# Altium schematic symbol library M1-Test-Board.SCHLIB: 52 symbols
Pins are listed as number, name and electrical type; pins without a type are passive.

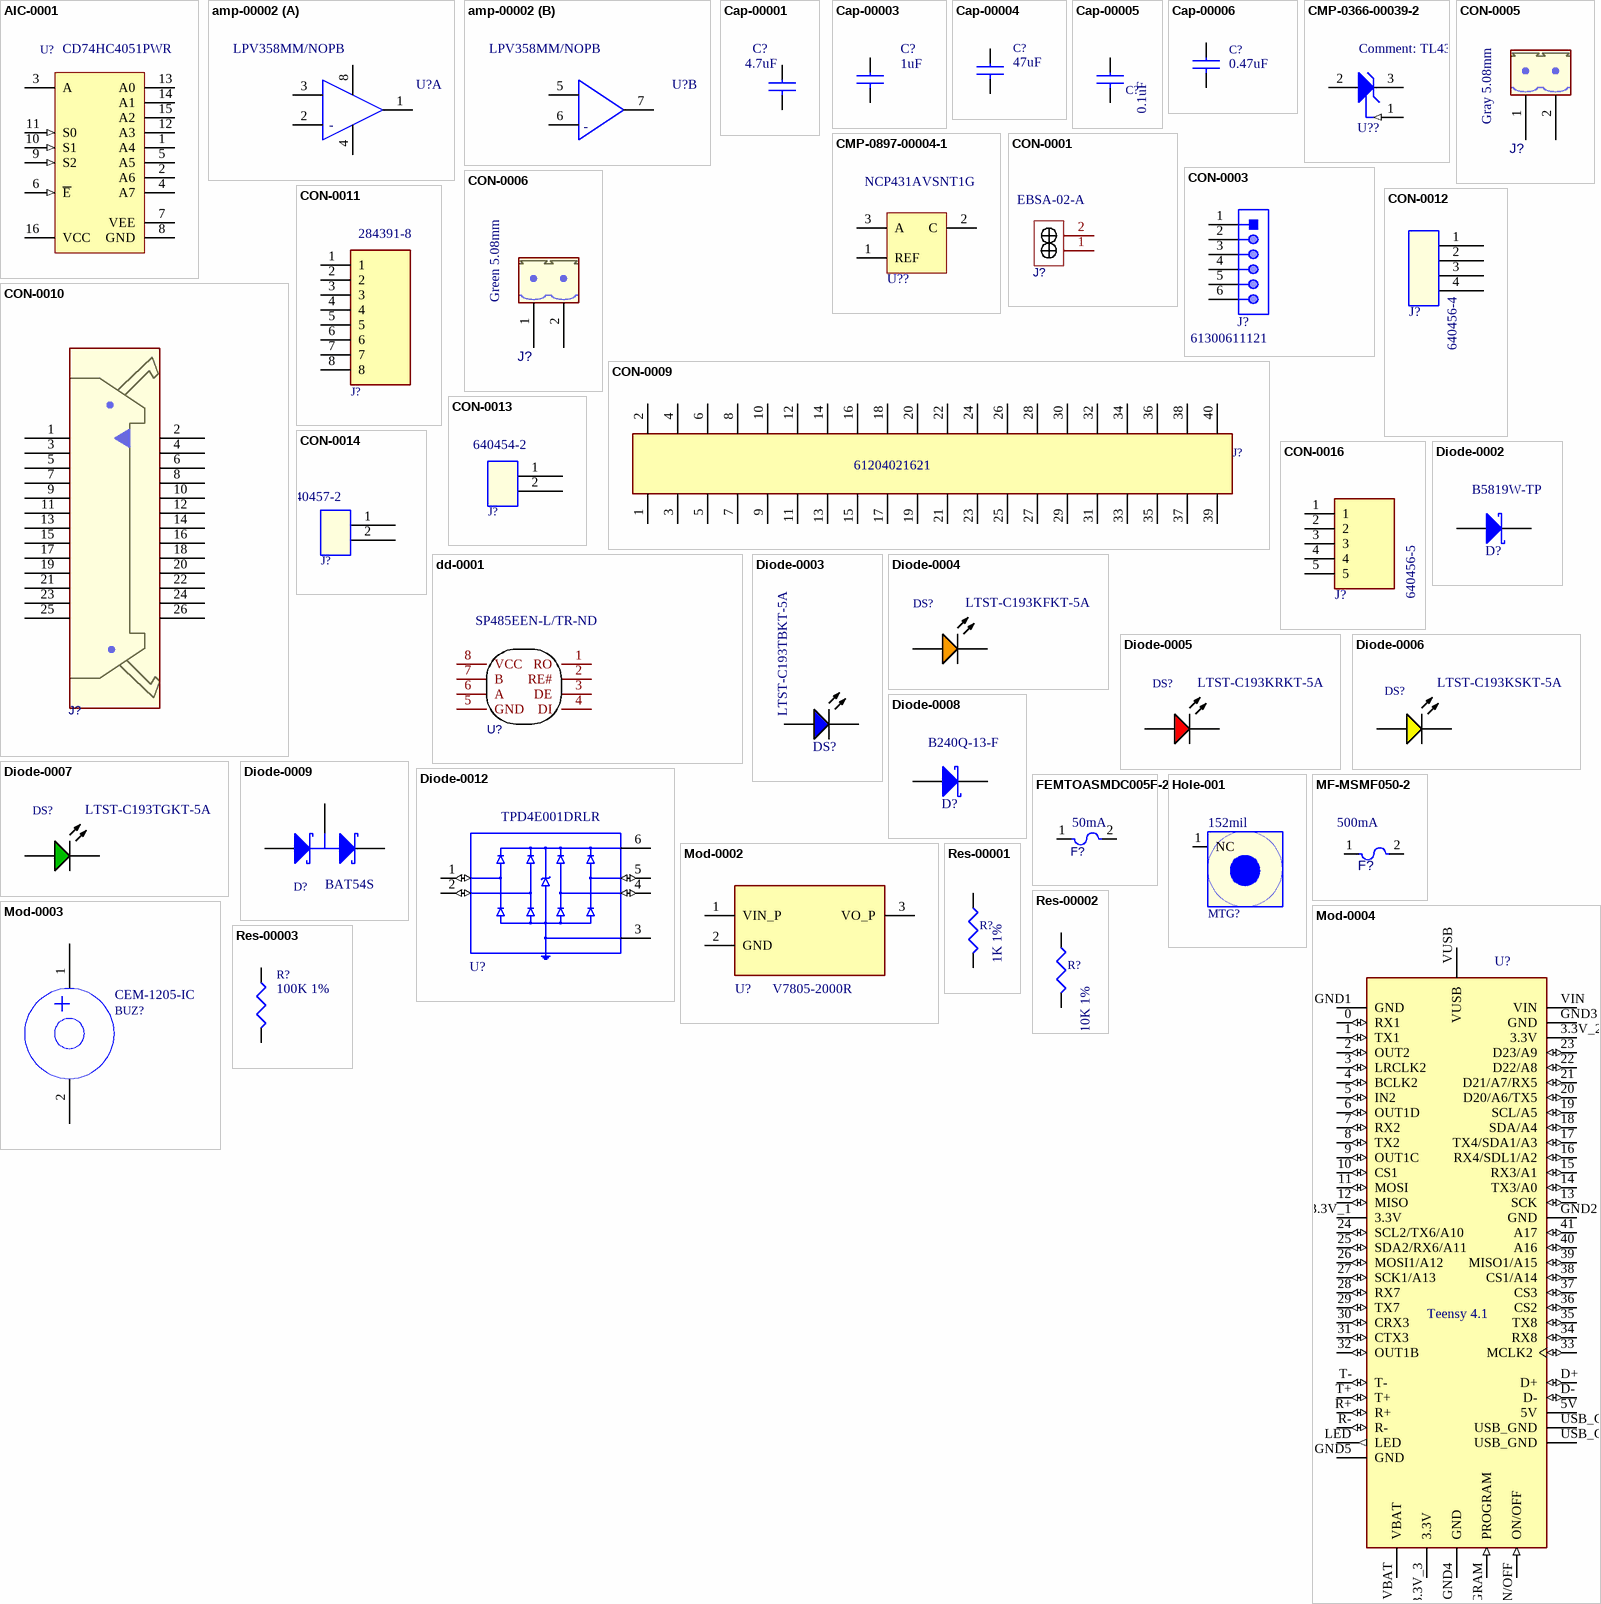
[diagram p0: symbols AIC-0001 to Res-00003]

## AIC-0001
designator U?, comment CD74HC4051PWR
5-V, 8: 1, 1-channel analog mutliplexer 16-TS; Manufacturer: Texas Instruments; Output Type: CMOS; VCC(Max)(V): 6; Ron(Typ)(Ohms): 45; Rating: Catalog; VCC(Min)(V): 2; Ron(Max)(Ohms): 130; Configuration: 1 X 1：8 MUX; Crosstalk: Yes; Bandwidth(Max)(MHz): 180; Bandwidth: 180MHz; Propagation Delay: 60ns; Number of Outputs: 1; Max Supply Voltage: 6V; Min Supply Voltage: 2V; Number of Inputs: 8; Min Dual Supply Voltage: 1V; Max Dual Supply Voltage: 5V; Dual Supply Voltage: 3V; Logic Function: Multiplexer,Demultiplexer; On-State Resistance: 130R; Turn-On Delay Time: 225ns; Supply Type: Single,Dual; Nominal Supply Current: 16uA; Polarity: Non-Inverting; Low Level Output Current: 25mA
footprint D0016A_N (SOIC, 16-Leads, Body 10x4mm, Pitch 1.27mm, IPC Medium Density)
footprint D0016A_L (SOIC, 16-Leads, Body 10x4mm, Pitch 1.27mm, IPC High Density)
footprint D0016A_M (SOIC, 16-Leads, Body 10x4mm, Pitch 1.27mm, IPC Low Density)
footprint 16-TSSOP-4.4mm
pins: 1 A4, 2 A6, 3 A, 4 A7, 5 A5, 6 ~{E} (in), 7 VEE (power), 8 GND (power), 9 S2 (in), 10 S1 (in), 11 S0 (in), 12 A3, 13 A0, 14 A1, 15 A2, 16 VCC (power)

## amp-00002
designator U?, comment LPV358MM/NOPB
Op Amp Dual Micropower Amplifier R-R O/P 5V 8; Manufacturer: TI National Semiconductor; Manufacturer: Texas Instruments; Manufacturer Part Number: LM358DR; Part Name: amp-00002; Output Current: 2mA; Min Dual Supply Voltage: 1.5V; Input Offset Voltage (Vos): 1.5mV; Power Supply Rejection Ratio (PSRR): 50dB; Unity Gain Bandwidth Product: 152kHz; Number of Channels: 2; Min Supply Voltage: 2.7V; Max Dual Supply Voltage: 16V; Output Current per Channel: 16mA; Dual Supply Voltage: 9V; Nominal Supply Current: 15uA; Slew Rate: 0.1V/µs; Input Bias Current: 2nA; Voltage Gain: 100dB; Operating Supply Voltage: 3V; Amplifier Type: GENERAL PURPOSE; Max Frequency: 1kHz
footprint FP-D0008A-MFG
footprint FP-D0008A-IPC_A
footprint FP-D0008A-IPC_B
footprint FP-D0008A-IPC_C
footprint MUA08A
part A pins: 1 1OUT, 2 IN1-, 3 IN1+, 4 V- (power), 8 V+ (power)
part B pins: 5 IN2+, 6 IN2-, 7 2OUT

## Cap-00001
designator C?, comment 4.7uF
CAP CER 4.7UF 16V X5R 0603; Part Name: Cap-00001; Manufacturer: Samsung; Manufacturer Part Number: CL10A475KO8NNNC; Material: Ceramic; Tolerance: 10%
footprint CC0603IPC
footprint C0603
pins: 1, 2

## Cap-00003
designator C?, comment 1uF
CAP CER 1UF 10V Y5V 0402; Part Name: Cap-00003; Manufacturer: KEMET; Manufacturer Part Number: C0402C105Z8VAC7867; Tolerance: 80%; Dielectric Material: Ceramic
footprint C0402
pins: 1, 2

## Cap-00004
designator C?, comment 47uF
CAP CER 47UF 16V X5R 1210; Part Name: Cap-00004; Manufacturer: Murata; Manufacturer Part Number: GRM32ER61C476ME15L; Tolerance: 20%; Dielectric Material: Ceramic
footprint C1210
pins: 1, 2

## Cap-00005
designator C?, comment 0.1uF
Cap Ceramic 0.1uF 50V X7R 10% Pad SMD 0402 125C Automotive T/R; Part Name: Cap-00005; Manufacturer: Murata; Manufacturer Part Number: GRT155R71H104KE01D
footprint C0402
pins: 1, 2

## Cap-00006
designator C?, comment 0.47uF
CAP CER 0.47UF 16V Y5V 0402; Part Name: Cap-00006; Manufacturer: Yageo; Manufacturer Part Number: CC0402ZRY5V7BB474; Tolerance: 80%; Capacitance: 470nF; Dielectric Material: Ceramic
footprint C0402
pins: 1, 2

## CMP-0366-00039-2
designator U??, comment TL431ACLP
Adjustable Precision Shunt Regulator, 34 ppm / degC, 100 mA, 0 to 70 degC, 3-pin TO-92 (LP), Pb-Free (RoHS); Manufacturer: Texas Instruments; VO Adj(Max)(V): 36; Initial Accuracy @ 25/deg C(%): 1; SubFamily: Shunt Voltage Reference; Temp Coeff(Typ)(ppm/ degree C): 34; VO Adj(Min)(V): 2.495; Rating: Catalog; Min Iz for Regulation(uA): 600; Temp Coeff(Max)(ppm/ degree C): 92; Iout/Iz(Max)(mA): 100
footprint LP0003A (TO, Flat Index; 3 In-Line, Formed Axial Leads; Body Dia. 4.8mm; Leads 0.56 x 0.41 mm (max))
pins: 1 REF (in), 2 ANODE, 3 CATHODE

## CMP-0897-00004-1
designator U??, comment NCP431AVSNT1G
Programmable Precision Reference, Low Cathode Current, Programmable, Shunt Regulator, 2.5 to 36 V, 0.04 to 100 mA, -40 to 125 degC, 3-Pin SOT23 (318), Pb-free, Tape and Reel; Manufacturer: ON Semiconductor; Tolerance: 1%; V(BR) Typ: 2.5 V; Tyep: Adjustable; VF Max: 36 V
footprint ONSC-SOT-23-3-318AP-08_V (SOT23, 3-Leads, Body 2.92x1.3mm, Pitch 0.95mm)
pins: 1 REF, 2 C, 3 A

## CON-0001
designator J?, comment EBSA-02-A
Conn Header Right angle 3.5 pitch 2P; Manufacturer: Adam Equipment; Connector Type: Male Pin; Number of Positions: 6; Pitch: 0.1inch
footprint WURTH691321100002-2PIN
footprint CONN-TH_2P-P3.50_JL15EDGRC-35002G01
pins: 1, 2

## CON-0003
designator J?, comment 61300611121
CONN HEADER 6 POS 2.54; Manufacturer: Wurth Electronics
footprint 61300611121
pins: 1, 2, 3, 4, 5, 6

## CON-0005
designator J?, comment Gray 5.08mm
Pluggable Term Blocks BCH-508HS- 2 GR 5.08; Manufacturer: Phoenix Contact; Manufacturer Part Number: 5433668; PKG: TB508HDR02_RTA; ATTR: HEADER TERM BLK 5.08MM 2POS RTA GREEN; Current Rating: 12A; Voltage Rating: 320V; Number of Positions Per Level: 2; Number of Levels: 1
footprint Conn_5442002
pins: 1, 2

## CON-0006
designator J?, comment Green 5.08mm
Pluggable Term Blocks BCH-508HS- 2 GN 5.08; Manufacturer: Phoenix Contact; Manufacturer Part Number: 5442002; ATTR: HEADER TERM BLK 5.08MM 2POS RTA GRAY; PKG: TB508HDR02_RTA; Connector Type: Screw; Number of Positions: 3; Pitch: 3.5mm; Current Rating: 13.5A; Voltage Rating: 200V; Gender: Male; Number of Levels: 1; Voltage: 300V; Approvals: UL,CSA,cULus,CB,EAC; Stripping Length: 5mm; Wire/Cable Gauge: 30AWG; Wire Gauge (Min): 16AWG
footprint Conn_5433668
pins: 1, 2

## CON-0009
designator J?, comment 61204021621
Male Box Header WR-BHD, THT, Vertical, pitch; Manufacturer: Wurth Electronics; Connector Type: Male Pin; Number of Positions: 40; Pitch: 0.1inch
footprint 61204021621
footprint IDC-TH_Z-231011040106
pins: 1, 2, 3, 4, 5, 6, 7, 8, 9, 10, 11, 12, 13, 14, 15, 16, 17, 18, 19, 20, 21, 22, 23, 24, 25, 26, 27, 28, 29, 30, 31, 32, 33, 34, 35, 36, 37, 38, 39, 40

## CON-0010
designator J?, comment N3429-5202RB
3000 Series; 2.54mm Pitch 26 Way 2 Row Right; Manufacturer: 3M; ATTR: CONN HEADER LATCH/EJEC  RTA DUAL ROW 26POS; PKG: 2M54_13x2_TH_LATCH; Connector Type: Male Pin; Number of Positions: 26; Current Rating: 1A; Voltage Rating: 300V; Gender: Male; Number of Positions Per Level: 8; Number of Levels: 1; Max Current Rating: 2A; Current: 12A; Shrouded: Yes (With); Tail Length: 3.5mm; Wire Gauge (Max): 30AWG; Row Spacing: 0.1inch; Closed End: No (Without); Plating: Brass; Thread Size: M2
footprint CONN_N3429-5202RB
pins: 1, 2, 3, 4, 5, 6, 7, 8, 9, 10, 11, 12, 13, 14, 15, 16, 17, 18, 19, 20, 21, 22, 23, 24, 25, 26

## CON-0011
designator J?, comment 284391-8
Conn Terminal Block F 8 POS 3.5mm Solder ST T; MF: TE Connectivity
footprint TE_284391-8
pins: 1, 2, 3, 4, 5, 6, 7, 8

## CON-0012
designator J?, comment 640456-4
Header, Friction Lock; MTA-100; 4; 250 VAC; P; Manufacturer: TE Connectivity; Connector Type: Connector,Pin,Plug,Header; Number of Positions: 4; Pitch: 2.54mm; Current Rating: 5A; Voltage Rating: 250V; Gender: Male; Contact Resistance: 6mR; Backwall/Post Interruptions: No (Without); Connector System: Wire-to-Board; PCB Mount Retention: Without; PCB Mounting Orientation: Vertical; Contact Style: Straight; Circuit Application: Signal; Mating Connector Lock: Yes (With); Plating Thickness: 3.81um; PCB Thickness: 0.063inch; Tail Length: 0.14inch; Contact Post Length: 3.56mm; Approvals: CSA; Underplate Material: Nickel
footprint CON$5C$4P$5C$100L
pins: 1, 2, 3, 4

## CON-0013
designator J?, comment 640454-2
Header, Polarized; MTA-100; 2; 250 VAC; Polye; Manufacturer: TE Connectivity; Parameter 1: C86502
footprint CON$5C$2P$5C$100LM
pins: 1, 2

## CON-0014
designator J?, comment 640457-2
MTA-100 HEADER  Friction Lock R/A 2POS 2.54MM; Manufacturer: AMP - TE CONNECTIVITY; Parameter 1: C86502
footprint TE_640457-2
pins: 1, 2

## CON-0016
designator J?, comment 640456-5
Connector 250V AC/DC 5A 5P 1 Row PCB - Vertic; Manufacturer: TE Connectivity; Connector Type: Connector,Pin,Plug,Header; Number of Positions: 5; Pitch: 2.54mm; Gender: Male; Contact Resistance: 6mR; Backwall/Post Interruptions: No (Without); Connector System: Wire-to-Board; PCB Mount Retention: Without; PCB Mounting Orientation: Vertical; Contact Style: Straight; Circuit Application: Signal; Mating Connector Lock: Yes (With); Plating Thickness: 3.81um; PCB Thickness: 0.063inch; Tail Length: 0.14inch; Contact Post Length: 3.56mm; Approvals: CSA
footprint TE_640456-5
pins: 1, 2, 3, 4, 5

## dd-0001
designator U?, comment SP485EEN-L/TR-ND
IC TXRX RS485 HALF DUPLEX 8SOIC; BOM_Manufacturer: EXAR; Part Name: dd-0001; Package Display: No; Data Rate: 10Mbps; Nominal Supply Current: 900uA; Max Power Dissipation: 550mW; Operating Supply Voltage: 5V; Number of Receivers: 1; Min Supply Voltage: 4.75V; Max Supply Voltage: 5.25V; Logic Function: Transceiver; Interface: RS-422,RS-485
footprint NSOIC-8
pins: 1 RO, 2 RE#, 3 DE, 4 DI, 5 GND, 6 A, 7 B, 8 VCC

## Diode-0002
designator D?, comment B5819W-TP
DIODE SCHOTTKY 40V 1A SOD323; Manufacturer: MCC; Manufacturer Part Number: B5819W TP; Forward Current: 25mA; Forward Voltage: 600mV @ 1A; Color: Blue; Dominant Wavelength: 470nm; Lens Style: Diffused,Colorless,Rectangular,Clear; Luminous Intensity: 28.5mcd; Number of Elements: 1; Power Dissipation: 110W; Reverse Voltage: 5V; Test Current: 20mA; Viewing Angle: 120°
footprint MCC-SOD123_V
pins: 1 A, 2 K

## Diode-0003
designator DS?, comment LTST-C193TBKT-5A
LED Blue CLEAR 0603 SMD; Manufacturer: Vishay Lite-On; Manufacturer: Rohm; Viewing Angle: 130°; Forward Voltage: 2.8V; Forward (Drive) Current: 20mA; Intensity: 22mcd; Lens Style: Diffused,Colorless,Rectangular,Clear; Luminous Intensity: 15mcd; Dominant Wavelength: 475nm; Number of Elements: 1; Power Dissipation: 76mW; Test Current: 5mA; Reverse Voltage: 5V; Lens Color: Colorless
footprint LED-BLUE_0603
pins: 1 A, 2 K

## Diode-0004
designator DS?, comment LTST-C193KFKT-5A
LED Orange CLEAR 0603 SMD; Manufacturer: Vishay Lite-On; Manufacturer: Rohm; Viewing Angle: 130°; Forward Voltage: 2.0V; Forward (Drive) Current: 20mA; Intensity: 22mcd; Lens Style: Diffused,Colorless,Rectangular,Clear; Forward Current: 5mA; Luminous Intensity: 28.1mcd; Dominant Wavelength: 605nm; Number of Elements: 1; Lens Color: Colorless
footprint ROHM-SMLE12BC7TT86_V (SMD, 2-Leads, Body 1.6x0.8mm)
footprint LED-ORANGE_0603
pins: 1 A, 2 K

## Diode-0005
designator DS?, comment LTST-C193KRKT-5A
LED RED CLEAR 0603 SMD; Manufacturer: Vishay Lite-On; Manufacturer: Broadcom Avago; Type: Uni-Color; Product Height (mm): 1.1mm; Power Dissipation: 50mW; Product Length (mm): 3.2mm; Forward Voltage: 2.0V; Luminous Intensity: 45mcd; DELETED: Compliant; Shape Type: Rectangular; Peak Wavelength: 660nm; Main Category: ChipLED; Dominant Wave Length: 639nm; Rad Hardened: No; Lens Type: ColorlessDiffused; Product Depth (mm): 1.6mm; Reverse Voltage: 5V; Forward Current: 5mA; Chip Material: GaAlAs; Test Current (It): 20mA; Lum Intensity: 17mcd; Viewing Angle: 130°; Number of  Elements: 1; Lens Style: Diffused,Colorless,Clear,Rectangular; Dominant Wavelength: 631nm; Lens Color: Colorless
footprint AVAG-HSMX-C150_V (SMD, 2-Leads, Body 3.2x1.6mm)
footprint LED-RED_0603
pins: 1 A, 2 K

## Diode-0006
designator DS?, comment LTST-C193KSKT-5A
LED Yellow CLEAR 0603 SMD; Manufacturer: Vishay Lite-On; Voltage Rating: 50 V; Power Rating: 75mW; Case\Package: 0603; Resistance: 390 Ohm; Forward Voltage: 2.0V; Lens Style: Diffused,Colorless,Rectangular; Viewing Angle: 130°; Forward Current: 30mA; Luminous Intensity: 45mcd; Dominant Wavelength: 594.5nm; Number of Elements: 1; Test Current: 5mA; Reverse Voltage: 5V; Lens Color: Colorless
footprint AVAG-HSMX-C190_V (SMD, 2-Leads, Body 1.6x0.8mm, Height 0.9mm)
footprint LED-YELLOW_0603
pins: 1 A, 2 K

## Diode-0007
designator DS?, comment LTST-C193TGKT-5A
LED Green CLEAR 0603 SMD; Manufacturer: Vishay Lite-On; Frequency: 400 KHz; Max Supply Voltage: 5.5 V; Access Time: 3500 ns; Clock Frequency: 100 KHz; Case\Package: SOIC; Density: 32 kb; Nominal Supply Current: 2 mA; Min Supply Voltage: 1.7 V; Max Reverse Voltage (DC): 40V; Average Rectified Current: 2A; Forward Voltage: 2.0V; Element Configuration: Single; Peak Non-Repetitive Surge Current: 50A; Lens Style: Diffused,Colorless,Rectangular; Viewing Angle: 130°; Forward Current: 5mA; Luminous Intensity: 280mcd; Dominant Wavelength: 535nm; Number of Elements: 1; Power Dissipation: 76mW; Reverse Voltage: 5V; Lens Color: Colorless; Max Reverse Current: 500uA
footprint AVAG-HSMX-C190_V (SMD, 2-Leads, Body 1.6x0.8mm, Height 0.9mm)
footprint LED-GREEN_0603
pins: 1 A, 2 K

## Diode-0008
designator D?, comment B240Q-13-F
Rectifier Diode Schottky 40V 2A Automotive 2-Pin SMB T/R; Manufacturer: Diodes; Manufacturer: MCC; Forward Current: 200mA; Forward Voltage: 800mV; Max Reverse Voltage (DC): 30V; Peak Non-Repetitive Surge Current: 600mA; Power Dissipation: 200mW; Max Reverse Current: 2uA; Capacitance: 10pF; Reverse Recovery Time: 5ns
footprint DIODE_DO214AA
pins: 1 A, 2 K

## Diode-0009
designator D?, comment BAT54S
DIODE SCHOTTKY 30V 150MA SOT23-3; Manufacturer: Sangdest Microelectronics; Manufacturer: ON Semiconductor / Fairchild; Recovery Time: 5ns; Package Version: Rev. 12, 03/2016; Peak Reverse Current: 2uA; Elements: 2
footprint FAIR-SOT23-3_V (SOT23, 3-Leads, Body 3.12x1.5mm, Pitch 0.95mm)
footprint sot23-3
pins: 1 A, 2 K, 3 C

## Diode-0012
designator U?, comment TPD4E001DRLR
TVS DIODE 5.5VWM SOT6; Manufacturer: Texas Instruments; Capacitance: 1.5pF; Max Power Dissipation: 100W; Breakdown Voltage: 11V; Direction: Unidirectional; Reverse Standoff Voltage: 5.5V; Clamping Voltage: 105.5V; Power Line Protection: Yes; Number of Channels: 4; Leakage Current: 1nA; Peak Pulse Current: 5.5A; Interface: LVDS,USB,Ethernet
footprint SOTFL50P160X60-6N
pins: 1 IO1 (io), 2 IO2 (io), 3 GND (power), 4 IO3 (io), 5 IO4 (io), 6 VCC (power)

## FEMTOASMDC005F-2
designator F?, comment 50mA
Ptc Reset Fuse 15V 50MA 0603; Manufacturer: Littelfuse; Manufacturer: Bourns; Manufacturer Part Number: FEMTOASMDC005F-2; Max Current Rating: 10A; Trip Current: 150mA; Time to Trip: 100ms
footprint F0603
pins: 1, 2

## Hole-001
designator MTG?, comment 152mil  (no BOM)
Plated; Part Name: Hole-001
footprint MNT-HOLE-169-350
pins: 1 NC

## MF-MSMF050-2
designator F?, comment 500mA
15VDC 500mA; Manufacturer: Bourns; Manufacturer Part Number: MF-MSMF050-2; Current Rating: 100A; Number of Terminals/Pins: 2; Trip Current: 1A; Voltage Rating: 15V; Resistance: 150mR; Power Dissipation: 800mW; Time to Trip: 0.15s; Aging: 1000 hr @ +85 °C (Passive); Approvals: UL,CSA,TUV
footprint BOUR-MF-MSMF050-2_V (SMD, 2-Leads, Body 4.55x3.24mm)
footprint FUSE_F050-2
pins: 1, 2

## Mod-0002
designator U?, comment V7805-2000R
Module DC-DC 12VIN 1-OUT 5V 2A 10W 3-Pin SIP Module; Manufacturer: CUI; Number of Outputs: 1; Efficiency: 91%; Min Input Voltage: 7V; Max Input Voltage: 18V; Isolation: Non-Isolated
footprint CONV_V7805-2000R
pins: 1 VIN_P (power), 2 GND (power), 3 VO_P (power)

## Mod-0003
designator BUZ?, comment CEM-1205-IC
12 mm, 5 Vdc, 92 dB, Through Hole, Driving Circuit, Magnetic Audio Indicator Buzzer; ADI Part Number: 3716-0001; Manufacturer: CUI Devices; S2 PN: S2-BZ-0001; Voltage: 5V; Current: 35mA; CLASS: DISCRETE; COMPSIDE: TOP; COMPLOC: [1301.000,1659.000]; COMPROT: 180; COMPGROUP: 0; COMPFIXED: NO; COMPHEIGHT: 0.000; PCB Footprint: BUZZ-MB5120C
footprint BUZZ-MB5120C
pins: 1 POS (power), 2 NEG (power)

## Mod-0004
designator U?, comment Teensy 4.1
Teensy 4.1 Development Board; Manufacturer: SparkFun; Manufacturer Part Number: DEV-16771
footprint MODULE_DEV-16771
footprint MODULE_DEV-16771 - headers
pins: 0 RX1 (io), 1 TX1 (io), 2 OUT2 (io), 3 LRCLK2 (io), 3.3V_1 3.3V (power), 3.3V_2 3.3V (power), 3.3V_3 3.3V (power), 4 BCLK2 (io), 5 IN2 (io), 5V (power), 6 OUT1D (io), 7 RX2 (io), 8 TX2 (io), 9 OUT1C (io), 10 CS1 (io), 11 MOSI (io), 12 MISO (io), 13 SCK (io), 14 TX3/A0 (io), 15 RX3/A1 (io), 16 RX4/SDL1/A2 (io), 17 TX4/SDA1/A3 (io), 18 SDA/A4 (io), 19 SCL/A5 (io), 20 D20/A6/TX5 (io), 21 D21/A7/RX5 (io), 22 D22/A8 (io), 23 D23/A9 (io), 24 SCL2/TX6/A10 (io), 25 SDA2/RX6/A11 (io), 26 MOSI1/A12 (io), 27 SCK1/A13 (io), 28 RX7 (io), 29 TX7 (io), 30 CRX3 (io), 31 CTX3 (io), 32 OUT1B (io), 33 MCLK2 (io), 34 RX8 (io), 35 TX8 (io), 36 CS2 (io), 37 CS3 (io), 38 CS1/A14 (io), 39 MISO1/A15 (io), 40 A16 (io), 41 A17 (io), D+ (io), D- (io), GND1 GND (power), GND2 GND (power), GND3 GND (power), GND4 GND (power), GND5 GND (power), LED (out), ON/OFF (in), PROGRAM (in), R+ (io), R- (io), T+ (io), T- (io), USB_GND1 USB_GND (power), USB_GND2 USB_GND (power), VBAT, VIN (power), VUSB

## Res-00001
designator R?, comment 1K 1%
Thick Film 0402 1K Ohm 1% 1/8W 0402; Part Name: Res-00001; Manufacturer: TE Connectivity; Manufacturer Part Number: CRGP0402F1K0; Max Power Dissipation: 125mW; Temperature Coefficient: 100ppm/°C; Power Rating: 0.125W
footprint R0402
pins: 1, 2

## Res-00002
designator R?, comment 10K 1%
Thick Film 0402 10K OHM 1% 1/16W 0402; Part Name: Res-00002; Manufacturer: Yageo; Manufacturer Part Number: RC0402FR-0710KP; Max Power Dissipation: 63mW; Temperature Coefficient: 150ppm/°C; Power Rating: 62.5mW
footprint CC0603IPC
footprint R0603
footprint R0402
pins: 1, 2

## Res-00003
designator R?, comment 100K 1%
Thick Film 0402 100K OHM 1% 1/16W 0402; Part Name: Res-00003; Manufacturer: Stackpole Electronics; Manufacturer Part Number: RMCF0402FT100K; Power Rating: 62.5mW
footprint CC0603IPC
footprint R0603
footprint R0402
pins: 1, 2

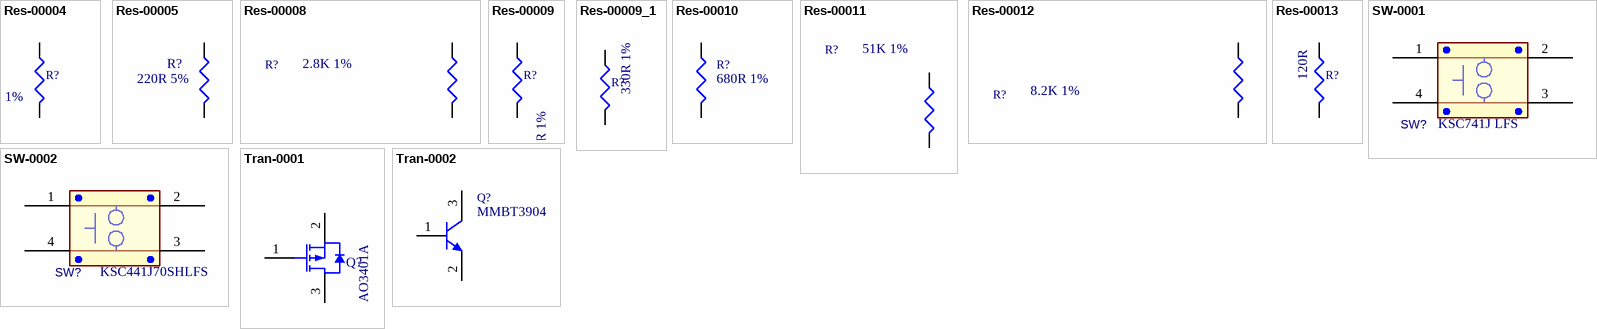
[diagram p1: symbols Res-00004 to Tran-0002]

## Res-00004
designator R?, comment 5.1K 1%
Thick Film 0402 5.1K Ohm 1% 1/16W 0402; Part Name: Res-00004; Manufacturer: Stackpole Electronics; Manufacturer Part Number: RMCF0402FT5K10; Max Power Dissipation: 63mW; Temperature Coefficient: 100ppm/°C; Power Rating: 62.5mW
footprint R0402
pins: 1, 2

## Res-00005
designator R?, comment 220R 5%
Thick Film  220 OHM 5% 1W 2512; Part Name: Res-00005; Manufacturer: Stackpole Electronics; Manufacturer Part Number: RMCF2512JT220R; Temperature Coefficient: 200ppm/°C
footprint RESC6331X75N
pins: 1, 2

## Res-00008
designator R?, comment 2.8K 1%
Thick Film 0402 2.8K Ohm 1% 0.063W ±100ppm/°C Molded SMD Paper T/R; Part Name: Res-00008; Manufacturer: Stackpole Electronics; Manufacturer Part Number: RMCF0402FT2K80; Resistance: 2.8kR; Max Power Dissipation: 63mW; Power Rating: 62.5mW
footprint R0402
pins: 1, 2

## Res-00009
designator R?, comment 330R 1%
Thick Film 0402 330 Ohm 1% 1/16W ±100ppm/°C Molded SMD Paper T/R; Part Name: Res-00009; Manufacturer: Yageo; Manufacturer Part Number: AF0402FR-07330RL; Max Power Dissipation: 63mW; Power Rating: 62.5mW
footprint R0402
pins: 1, 2

## Res-00009_1
designator R?, comment 330R 1%
Thick Film 0402 120 Ohm 1% 1/16W ±100ppm/°C Molded SMD Paper T/R; Part Name: Res-00009; Manufacturer: Yageo; Manufacturer Part Number: AF0402FR-07330RL; Max Power Dissipation: 63mW; Power Rating: 62.5mW
footprint R0402
pins: 1, 2

## Res-00010
designator R?, comment 680R 1%
Thick Film 0402 680 Ohm 1% 0.063W(1/16W) ±100ppm/C Pad SMD Automotive T/R; Part Name: Res-00010; Manufacturer: Stackpole Electronics; Manufacturer Part Number: RMCF0402FT680R; Max Power Dissipation: 63mW; Temperature Coefficient: 100ppm/°C; Power Rating: 62.5mW
footprint R0402
pins: 1, 2

## Res-00011
designator R?, comment 51K 1%
Res Thick Film 0402 51K Ohm 1% 0.063W(1/16W) ±100ppm/C Pad SMD Automotive T/R; Part Name: Res-00011; Manufacturer: Stackpole Electronics; Manufacturer Part Number: RMCF0402FT51K0; Resistance: 51kR; Max Power Dissipation: 63mW; Temperature Coefficient: 100ppm/°C
footprint R0402
pins: 1, 2

## Res-00012
designator R?, comment 8.2K 1%
Res Thick Film 0402 8.2K Ohm 5% 0.063W ±100ppm/°C Molded SMD Paper T/R; Part Name: Res-00012; Manufacturer: Stackpole Electronics; Manufacturer Part Number: RMCF0402JT8K20; Resistance: 8.2kR; Max Power Dissipation: 63mW
footprint R0402
pins: 1, 2

## Res-00013
designator R?, comment 120R
Res Thick Film 0402 120 Ohm 1% 0.063W(1/16W) ±100ppm/C Pad SMD Automotive T/R; Part Name: Res-00013; Manufacturer: Stackpole Electronics; Manufacturer Part Number: RMCF0402FT120R; Max Power Dissipation: 63mW; Temperature Coefficient: 100ppm/°C
footprint R0402
pins: 1, 2

## SW-0001
designator SW?, comment KSC741J LFS
Switch Tactile N.O. SPST Round Button J-Bend; Part Name: SW-0001; Manufacturer: ITT C&K; Mechanical Life: 300000Cycles; Actuator Color: Blue; Operating Force: 4N; Max Current Rating: 50mA; Voltage Rating (DC): 32V; Illumination Type: Non-Illuminated; Switch Function: Off-Mom; Actuator Type: Standard; Switch Travel: 0.4mm; Actuator Length: 1.7mm; Power Rating: 1W; Ratings: IP67,Waterproof,Dust Tight
footprint SON4_KSC741JLFS_CNK-blue
pins: 1, 2, 3, 4

## SW-0002
designator SW?, comment KSC441J70SHLFS
Switch Tactile N.O. SPST Round Button J-Bend; Part Name: SW-0002; Manufacturer: ITT C&K; Actuator Material: Nylon,Polyamide,PA66; Mechanical Life: 300000Cycles; Operating Force: 5N; Max Current Rating: 50mA; Voltage Rating (DC): 32V; Illumination Type: Non-Illuminated,Illuminated; Switch Function: Off-Mom; Actuator Type: Standard; Switch Travel: 0.75mm; Actuator Length: 2.6mm; Power Rating: 1W
footprint SON4_KSC741JLFS_CNK-red
pins: 1, 2, 3, 4

## Tran-0001
designator Q?, comment AO3401A
Mosfet P-channel 30V 4A SOT23-3; Manufacturer: Alpha & Omega Semiconductor; Manufacturer Part Number: AO3401AL; Output Power (Max): NotRequiredW; Power Dissipation: 350mW; Rad Hardened: No; Drain Efficiency: NotRequired%; Noise Figure: NotRequireddB; Frequency (Max): NotRequiredMHz; Number of  Elements: 1; Gate-Source Voltage (Max): ?12V; Channel Mode: Enhancement; Drain-Source On-Res: 0.044ohm; Type: PowerMOSFET; Polarity: NPN; Rds On Max: 50mR; Input Capacitance: 645pF; Max Power Dissipation: 1.4W; Collector Base Voltage (VCBO): 60V; Collector Emitter Breakdown Voltage: 40V; Collector Emitter Saturation Voltage: 300mV; Current Rating: 200mA; Element Configuration: Single; Emitter Base Voltage (VEBO): 6V; Frequency: 300MHz; hFE Min: 100
footprint AO-SOT-23-3L_V (SOT23, 3-Leads, Body 3.1x1.8mm, Pitch 0.95mm)
pins: 1 GATE, 2 SOURCE, 3 DRAIN

## Tran-0002
designator Q?, comment MMBT3904
Trans GP BJT NPN 60V 0.2A 350mW Automotive 3-Pin SOT-23 T/R; Manufacturer: ON Semiconductor / Fairchild; Manufacturer: ON Semiconductor; Elements: 1; Power: 225mW; Frequency: 250MHz; Vce Max: 300mV; Max Collector Current: 200mA; Collector-emitter Voltage-Max: 400mV
footprint ONSC-SOT-23-3-318-08_V (SOT23, 3-Leads, Body 3.04x1.4mm, Pitch 0.95mm)
footprint sot23-3
pins: 1 B, 2 E, 3 C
